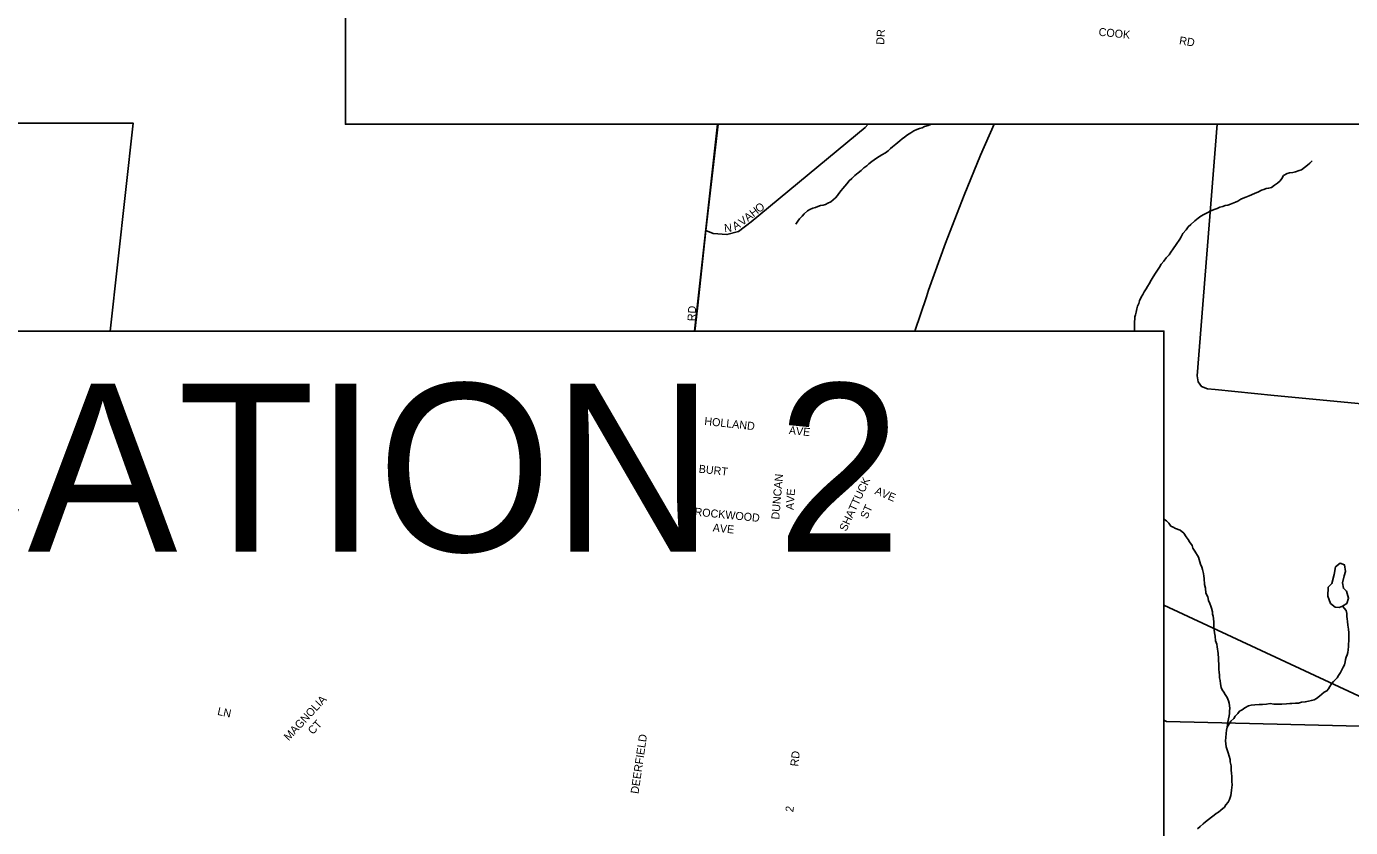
# Model space of a CAD drawing. Extents: x 0 to 34, y -4 to 22.
# Drawn here: x 5.277 to 6.381, y 19.435 to 20.103 of the extents above; entities that cross this region are included whole.
import ezdxf

# ---------------------------------------------------------------- set-up
doc = ezdxf.new("R2010")
doc.units = 0
for name, color, linetype in [('GM_X_City_Street', 7, 'Continuous'), ('GM_X_City_Street_Text', 7, 'Continuous'), ('GM_X_Corporation', 7, 'Continuous'), ('GM_X_Minor_Lake', 7, 'Continuous'), ('GM_X_Minor_River', 7, 'Continuous'), ('GM_X_Section', 7, 'Continuous'), ('GM_X_State_Route', 7, 'Continuous'), ('GM_X_Township_Subdivision_Text', 7, 'Continuous'), ('SH_Text', 7, 'Continuous'), ('TX_P_100', 7, 'Continuous')]:
    doc.layers.add(name, color=color, linetype=linetype)

msp = doc.modelspace()

# ---------------------------------------------------------------- linework, layer by layer
at = {"layer": 'GM_X_City_Street'}
for points in [[(5.8343, 19.8488), (5.8363, 19.868), (5.8434, 19.9328), (5.8536, 20.0213)], [(5.8434, 19.9328), (5.8495, 19.9303), (5.861, 19.9293), (5.8707, 19.9317), (5.881, 19.9398), (5.976, 20.0185), (5.9785, 20.0213)], [(6.2695, 20.0213), (6.2526, 19.8114), (6.2535, 19.8065), (6.2563, 19.8026), (6.2613, 19.8007), (6.2676, 19.8), (6.3168, 19.7952), (6.4367, 19.7836), (6.438, 19.7835)]]:
    msp.add_lwpolyline(points, dxfattribs=at)
at = {"layer": 'GM_X_Corporation'}
for points in [[(6.473, 20.0213), (5.5431, 20.0213), (5.5431, 20.478), (6.6093, 20.478)], [(5.2674, 20.0221), (5.3661, 20.0222), (5.347, 19.8488), (6.225, 19.8488), (6.225, 19.5243), (6.2273, 19.5233), (6.4231, 19.5186)]]:
    msp.add_lwpolyline(points, dxfattribs=at)
at = {"layer": 'GM_X_Minor_Lake'}
for points in [[(6.3751, 19.6448), (6.3763, 19.6485), (6.3756, 19.6539), (6.3719, 19.6553), (6.368, 19.6522), (6.3668, 19.6458), (6.365, 19.6383), (6.362, 19.6352)], [(6.362, 19.6352), (6.3616, 19.6277), (6.3638, 19.6218), (6.3678, 19.6185), (6.371, 19.6184), (6.3739, 19.6194), (6.3775, 19.6217), (6.3789, 19.6262), (6.3772, 19.6319), (6.3746, 19.6344), (6.3739, 19.6389), (6.3751, 19.6448)]]:
    msp.add_lwpolyline(points, dxfattribs=at)
at = {"layer": 'GM_X_Minor_River'}
for points in [[(6.0314, 20.0213), (6.0286, 20.0201), (6.0256, 20.0194), (6.0237, 20.0184), (6.0215, 20.0177), (6.0193, 20.0169), (6.0166, 20.0157), (6.0142, 20.0142), (6.0114, 20.0124), (6.009, 20.0106), (6.007, 20.009), (6.0051, 20.0075), (6.0018, 20.0046)], [(6.0018, 20.0046), (5.999, 20.0023), (5.9971, 20.0011), (5.9952, 19.9992), (5.993, 19.9974), (5.99, 19.9957), (5.9878, 19.9944), (5.9856, 19.9929), (5.9837, 19.9916), (5.9818, 19.9903), (5.9793, 19.9882), (5.9774, 19.9867), (5.9749, 19.9849), (5.9727, 19.9828), (5.9702, 19.9808), (5.9674, 19.9785), (5.9649, 19.9759), (5.9627, 19.9741), (5.9608, 19.9717), (5.9591, 19.9696), (5.9574, 19.9678), (5.956, 19.966), (5.9541, 19.9636), (5.953, 19.9618), (5.9513, 19.96), (5.9494, 19.9582), (5.9474, 19.9566), (5.945, 19.9554), (5.9431, 19.9544), (5.9412, 19.9539), (5.939, 19.9534), (5.9366, 19.9527), (5.9347, 19.9519), (5.9325, 19.9512), (5.9301, 19.9502), (5.9282, 19.9492), (5.9254, 19.9466), (5.9235, 19.9445), (5.9215, 19.9425), (5.9201, 19.9404), (5.9184, 19.938)], [(6.3173, 19.9704), (6.3198, 19.9722), (6.322, 19.9742), (6.3234, 19.976), (6.3248, 19.9784), (6.3276, 19.9802), (6.3297, 19.9807), (6.3324, 19.9811), (6.3346, 19.9816), (6.3376, 19.9826), (6.3397, 19.9833), (6.3422, 19.9851), (6.3447, 19.9872), (6.3466, 19.9887), (6.3485, 19.9908)], [(6.2006, 19.8488), (6.2006, 19.8494), (6.2004, 19.8529), (6.2005, 19.8548), (6.2005, 19.8569), (6.2009, 19.8588), (6.2009, 19.8607), (6.2013, 19.8625), (6.2019, 19.8646), (6.2025, 19.8673), (6.2031, 19.8697), (6.204, 19.8718), (6.2048, 19.8739), (6.206, 19.8771), (6.2074, 19.8794), (6.2086, 19.8815), (6.2103, 19.8841), (6.2114, 19.886), (6.2128, 19.8883), (6.2145, 19.8912), (6.2162, 19.8941), (6.2179, 19.897), (6.2196, 19.8996), (6.2213, 19.9022), (6.2227, 19.9046), (6.225, 19.9072), (6.2269, 19.9098), (6.2294, 19.9124), (6.2308, 19.9145), (6.2328, 19.9174), (6.2353, 19.9211), (6.2382, 19.9255), (6.2393, 19.9273), (6.2407, 19.9302), (6.2435, 19.9331), (6.2452, 19.9357), (6.2474, 19.9378), (6.2507, 19.9406), (6.2535, 19.9429), (6.2557, 19.9445), (6.2584, 19.946), (6.2611, 19.9475), (6.2641, 19.949), (6.2676, 19.9505), (6.2695, 19.951), (6.2717, 19.952), (6.2742, 19.9527), (6.2761, 19.9535), (6.2782, 19.9539), (6.2804, 19.9547), (6.2847, 19.9564), (6.2866, 19.9571), (6.2891, 19.9587), (6.291, 19.9597), (6.2932, 19.9604), (6.2961, 19.9617), (6.3005, 19.9634), (6.3038, 19.9649), (6.3062, 19.9662), (6.3084, 19.9669), (6.3103, 19.9676), (6.3124, 19.9681), (6.3146, 19.9686), (6.3173, 19.9704)], [(6.2812, 19.4831), (6.281, 19.4863), (6.2803, 19.4898), (6.2801, 19.4917), (6.2794, 19.4944), (6.2787, 19.4973), (6.2777, 19.4998), (6.277, 19.5022), (6.2765, 19.5046), (6.2763, 19.5073), (6.2767, 19.5099), (6.2768, 19.5134), (6.2772, 19.5161), (6.2778, 19.5187), (6.2782, 19.5227), (6.2788, 19.5254), (6.2794, 19.528), (6.2798, 19.5299), (6.2798, 19.5323), (6.2799, 19.5342), (6.2797, 19.5366), (6.2795, 19.5387), (6.2788, 19.5406), (6.2778, 19.5433), (6.276, 19.5458), (6.275, 19.5479), (6.2737, 19.5498), (6.2727, 19.5517), (6.2723, 19.5547), (6.2718, 19.5574), (6.2714, 19.5598), (6.2714, 19.5619), (6.271, 19.5644), (6.2708, 19.5668), (6.2709, 19.5692), (6.2707, 19.5716), (6.2705, 19.5737), (6.2706, 19.5759), (6.2702, 19.5799), (6.2693, 19.5855), (6.2691, 19.5879), (6.2681, 19.5906), (6.2677, 19.5944), (6.2672, 19.5973), (6.2668, 19.5997), (6.2666, 19.603), (6.2665, 19.6062), (6.2663, 19.6091), (6.2661, 19.611), (6.2656, 19.6129), (6.2654, 19.6148), (6.2647, 19.6177), (6.264, 19.6196), (6.2632, 19.6218), (6.2622, 19.6242), (6.2615, 19.6272), (6.26, 19.6304), (6.2596, 19.6344), (6.2589, 19.6374), (6.2586, 19.6425), (6.2584, 19.6444), (6.2579, 19.6468), (6.2572, 19.65), (6.2567, 19.6519), (6.2555, 19.6546), (6.2543, 19.6584), (6.2538, 19.6603), (6.2507, 19.6652), (6.2492, 19.6679), (6.2485, 19.67), (6.2464, 19.673), (6.2452, 19.675), (6.2436, 19.6774), (6.2416, 19.6804), (6.2385, 19.6829), (6.2347, 19.6841), (6.2326, 19.6852), (6.2308, 19.6863), (6.229, 19.6888), (6.2272, 19.6905), (6.225, 19.692)], [(6.2778, 19.5187), (6.2809, 19.5237), (6.2834, 19.5258), (6.2845, 19.5279), (6.2867, 19.5299), (6.2881, 19.5318), (6.2903, 19.533), (6.2925, 19.5348), (6.2955, 19.5364), (6.2977, 19.5368), (6.3009, 19.5373), (6.3044, 19.5374), (6.3073, 19.5376), (6.3106, 19.5378), (6.3135, 19.5382), (6.3167, 19.5378), (6.3194, 19.5378), (6.3234, 19.5379), (6.3272, 19.538), (6.3299, 19.5382), (6.3317, 19.5382), (6.3347, 19.5386), (6.3371, 19.5385), (6.3398, 19.5393), (6.3428, 19.5397), (6.3455, 19.5404), (6.3479, 19.5409), (6.3503, 19.5413), (6.3522, 19.5424), (6.3547, 19.5444), (6.3566, 19.546), (6.3586, 19.5478), (6.3608, 19.5488), (6.3622, 19.5506), (6.3633, 19.5524), (6.3647, 19.5548), (6.3664, 19.5566), (6.3694, 19.5597), (6.3706, 19.5616), (6.3722, 19.5642), (6.3734, 19.5663), (6.3745, 19.5687), (6.3754, 19.5705), (6.376, 19.5731), (6.3764, 19.575), (6.377, 19.5769), (6.3778, 19.579), (6.3782, 19.5808), (6.3785, 19.5832), (6.3789, 19.5859), (6.3787, 19.588), (6.379, 19.5902), (6.3791, 19.592), (6.3791, 19.5944), (6.379, 19.5971), (6.3788, 19.6003), (6.3784, 19.6035), (6.3779, 19.6067), (6.3777, 19.6089), (6.3773, 19.6108), (6.3774, 19.6134), (6.3769, 19.6159), (6.3739, 19.6194)], [(6.253, 19.4337), (6.2552, 19.4358), (6.2577, 19.4381), (6.2596, 19.4397), (6.2621, 19.4415), (6.2646, 19.4435), (6.2668, 19.4453), (6.2687, 19.4466), (6.2706, 19.4476), (6.2725, 19.4494), (6.2756, 19.452), (6.2767, 19.4538), (6.2787, 19.4562), (6.2798, 19.4583), (6.2807, 19.4615), (6.281, 19.4636), (6.2814, 19.466), (6.2815, 19.4684), (6.2818, 19.4705), (6.2816, 19.4732), (6.2817, 19.4753), (6.2815, 19.4777), (6.2813, 19.4801), (6.2812, 19.4831)]]:
    msp.add_lwpolyline(points, dxfattribs=at)
at = {"layer": 'GM_X_Section'}
for points in [[(5.8339, 19.8488), (5.853, 20.0213), (5.5431, 20.0213), (5.5431, 20.1566), (5.1497, 20.1935), (5.1104, 19.8488)], [(5.7836, 19.3921), (5.7814, 19.3717), (6.4863, 19.299), (6.5597, 20.0213), (5.853, 20.0213), (5.8339, 19.8488), (6.225, 19.8488), (6.225, 19.3921)]]:
    msp.add_lwpolyline(points, close=True, dxfattribs=at)
at = {"layer": 'GM_X_State_Route'}
msp.add_lwpolyline([(6.0175, 19.8488), (6.0272, 19.8774), (6.029, 19.8828), (6.0431, 19.922), (6.0585, 19.9621), (6.0721, 19.9954), (6.0837, 20.0213)], dxfattribs=at)
at = {"layer": 'SH_Text'}
for points in [[(5.5431, 20.478), (5.5431, 20.0213), (7.8251, 20.0213), (7.8251, 20.478)], [(3.9436, 19.8488), (6.225, 19.8488), (6.225, 19.3921), (3.9436, 19.3921)]]:
    msp.add_lwpolyline(points, close=True, dxfattribs=at)
at = {"layer": 'TX_P_100'}
msp.add_lwpolyline([(6.225, 19.3921), (6.9466, 19.284), (6.225, 19.6204)], close=True, dxfattribs=at)

# ---------------------------------------------------------------- texts
at = {"layer": 'GM_X_City_Street_Text'}
for s, rotation, p in [('DR', 86.989, (5.9919, 20.0874)), ('COOK', 354.2872, (6.1704, 20.0951)), ('RD', 351.0327, (6.2374, 20.088)), ('V', 38.0661, (5.8738, 19.9362)), ('A', 38.5144, (5.8785, 19.9398)), ('H', 38.496, (5.8831, 19.9435)), ('O', 38.4985, (5.8877, 19.9471)), ('N', 4.5077, (5.8589, 19.9313)), ('A', 29.0299, (5.8677, 19.9327)), ('RD', 86.989, (5.8347, 19.8569)), ('HOLLAND', 353.946, (5.8419, 19.7706)), ('AVE', 354.0969, (5.9123, 19.763)), ('BURT', 353.8278, (5.8372, 19.7308)), ('DUNCAN', 85.1551, (5.9045, 19.6915)), ('SHATTUCK', 65.1711, (5.9603, 19.6813)), ('AVE', 86.0574, (5.9165, 19.6995)), ('A', 338.917, (5.9836, 19.7131)), ('V', 337.407, (5.989, 19.711)), ('E', 337.1637, (5.9944, 19.7087)), ('ST', 64.9823, (5.9777, 19.6917)), ('ROCKWOOD', 354.4283, (5.8337, 19.695)), ('AVE', 354.0977, (5.8489, 19.6818)), ('DEERFIELD', 81.655, (5.7872, 19.4627)), ('RD', 83.6625, (5.9203, 19.4856)), ('2', 83.2946, (5.9162, 19.4475))]:
    msp.add_text(s, height=0.00667, rotation=rotation, dxfattribs=at).set_placement(p)
at = {"layer": 'GM_X_Township_Subdivision_Text'}
for s, rotation, p in [('MAGNOLIA', 47.122, (5.4959, 19.5068)), ('LN', 348.105, (5.436, 19.5289)), ('CT', 47.2983, (5.516, 19.512))]:
    msp.add_text(s, height=0.00667, rotation=rotation, dxfattribs=at).set_placement(p)
at = {"layer": 'SH_Text'}
msp.add_text('PROJECT LOCATION 2', height=0.14, dxfattribs=at).set_placement((3.9676, 19.665))

doc.saveas('drawing.dxf')
